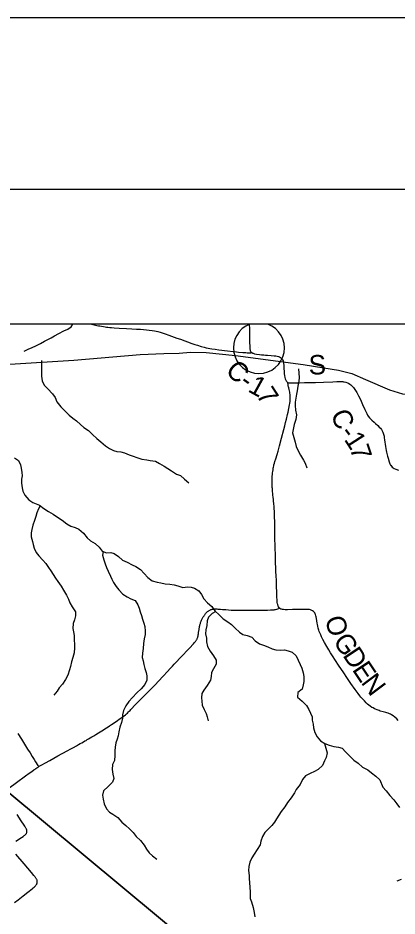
# Model space of a CAD drawing. Extents: x 0 to 34, y 0 to 22.
# Drawn here: x 21.722 to 22.828, y 19.377 to 22 of the extents above; entities that cross this region are included whole.
import ezdxf

# ---------------------------------------------------------------- set-up
doc = ezdxf.new("R2010")
doc.units = 0
for name, color, linetype in [('GM_X_Corporation', 7, 'Continuous'), ('GM_X_County_Road', 7, 'Continuous'), ('GM_X_County_Road_Text', 7, 'Continuous'), ('GM_X_Minor_River', 7, 'Continuous'), ('GM_X_Rail_Line', 7, 'Continuous'), ('GM_X_State_Shield', 7, 'Continuous'), ('GM_X_Township_Road', 7, 'Continuous'), ('GM_X_Unincorporated_Location', 7, 'Continuous'), ('SH_Border', 7, 'Continuous'), ('SH_Cut_Line', 7, 'Continuous')]:
    doc.layers.add(name, color=color, linetype=linetype)

msp = doc.modelspace()

# ---------------------------------------------------------------- linework, layer by layer
at = {"layer": 'GM_X_Corporation'}
for points in [[(17.597, 14.3059), (23.9625, 14.3059), (23.9625, 21.1059), (18.23, 21.1059), (18.203, 20.7746), (18.1731, 20.4696), (18.0879, 19.5959), (18.0387, 19.0962), (17.9672, 18.2605), (17.8718, 17.2256), (17.7834, 16.317), (17.7373, 15.7617), (17.7239, 15.6245), (17.6136, 14.4601)], [(23.8219, 21.1059), (19.1325, 21.1059), (19.4417, 20.9771), (20.0591, 20.7271), (20.5209, 20.5272), (20.9887, 20.3291), (21.1503, 20.1924), (21.2024, 20.1483), (21.462, 19.9289), (21.6862, 19.7442), (22.4736, 19.0897), (22.5453, 19.0171), (22.8523, 19.0143), (22.8728, 18.8666), (23.8372, 18.7818), (23.8567, 18.7798), (23.8401, 19.9225), (23.83, 20.7057)]]:
    msp.add_lwpolyline(points, close=True, dxfattribs=at)
msp.add_lwpolyline([(23.1639, 16.2517), (23.362, 16.8676), (23.4462, 17.1725), (23.5619, 17.5912), (23.566, 17.6066), (23.6615, 17.9524), (23.7107, 18.1304), (23.8507, 18.7519), (23.8567, 18.7798), (23.8372, 18.7818), (22.8728, 18.8666), (22.8523, 19.0143), (22.5453, 19.0171), (22.4736, 19.0897), (21.6862, 19.7442)], dxfattribs=at)
at = {"layer": 'GM_X_County_Road'}
for points in [[(21.9364, 21.1059), (21.9479, 21.1031), (21.9517, 21.1022), (21.9567, 21.1012), (21.961, 21.1004), (21.966, 21.0994), (21.9713, 21.0986), (21.9762, 21.0978), (21.9801, 21.0972), (21.9842, 21.0967), (21.9895, 21.0961), (21.9948, 21.0957), (22.0026, 21.0952), (22.0174, 21.0943), (22.0385, 21.0932), (22.0541, 21.0924), (22.0679, 21.0915), (22.0791, 21.0907), (22.0885, 21.0899), (22.0972, 21.0891), (22.1046, 21.0882), (22.1134, 21.087), (22.1203, 21.0859), (22.1255, 21.0849), (22.13, 21.0839), (22.1368, 21.0821), (22.1458, 21.0795), (22.1517, 21.0775), (22.1624, 21.0736), (22.1857, 21.0651), (22.1956, 21.0616), (22.2288, 21.0497), (22.2379, 21.0466), (22.2458, 21.044), (22.2566, 21.0407), (22.2647, 21.0384), (22.2709, 21.0368), (22.2768, 21.0354), (22.2813, 21.0345), (22.2871, 21.0337), (22.2968, 21.0325), (22.3078, 21.0312), (22.3332, 21.0282), (22.3501, 21.0262), (22.3595, 21.025), (22.3649, 21.0244), (22.3781, 21.0232), (22.3868, 21.0225), (22.3907, 21.0222), (22.3961, 21.0217), (22.3988, 21.0217), (22.4018, 21.0221), (22.4039, 21.0228)], [(22.4039, 21.0228), (22.4026, 21.0239), (22.4014, 21.0253), (22.4006, 21.0272), (22.3999, 21.0294), (22.3995, 21.0318), (22.3991, 21.0355), (22.399, 21.0395), (22.3989, 21.0436), (22.3988, 21.05), (22.3985, 21.0621), (22.3982, 21.0796), (22.398, 21.092), (22.3978, 21.1059)], [(22.4039, 21.0228), (22.4062, 21.0213), (22.4084, 21.0206), (22.4124, 21.0195), (22.4178, 21.0185), (22.4269, 21.0171), (22.432, 21.0165), (22.4393, 21.0157), (22.4441, 21.0152), (22.4499, 21.0148), (22.461, 21.014), (22.4696, 21.0134), (22.474, 21.0129), (22.478, 21.0121), (22.4817, 21.0111), (22.485, 21.0098), (22.4879, 21.0083), (22.4904, 21.0062), (22.4925, 21.0037), (22.4941, 21.0011), (22.4954, 20.9982), (22.4964, 20.9949), (22.497, 20.991), (22.4973, 20.9857), (22.4978, 20.9752), (22.4983, 20.9681), (22.4986, 20.9648), (22.499, 20.9607), (22.4998, 20.9553), (22.5008, 20.9504), (22.5018, 20.9465), (22.5027, 20.9441), (22.5035, 20.9424), (22.5048, 20.9398), (22.506, 20.9381), (22.5072, 20.9367), (22.5088, 20.9354), (22.5099, 20.9346)], [(22.4856, 20.276), (22.4842, 20.2773), (22.4825, 20.2797), (22.4809, 20.2829), (22.4802, 20.2846), (22.4796, 20.2869), (22.4791, 20.2893), (22.4786, 20.2928), (22.4783, 20.2967), (22.478, 20.3007), (22.4776, 20.3087), (22.4772, 20.3187), (22.4769, 20.3259), (22.4765, 20.3366), (22.4762, 20.3425), (22.4757, 20.3556), (22.4751, 20.3712), (22.4747, 20.3819), (22.4743, 20.3936), (22.4737, 20.4091), (22.4733, 20.4231), (22.4729, 20.4357), (22.4726, 20.4473), (22.4723, 20.4583), (22.4718, 20.4795), (22.4716, 20.49), (22.4711, 20.5241), (22.4709, 20.5312), (22.4708, 20.5396), (22.4705, 20.5479), (22.4701, 20.5553), (22.4699, 20.5601), (22.4696, 20.5652), (22.4691, 20.5725), (22.4684, 20.5817), (22.4678, 20.5884), (22.4673, 20.5934), (22.4666, 20.6006), (22.4659, 20.6065), (22.4654, 20.611), (22.4648, 20.6173), (22.4643, 20.6224), (22.4641, 20.626), (22.464, 20.6289), (22.4636, 20.6354), (22.4635, 20.6425), (22.4637, 20.6509), (22.4638, 20.6566), (22.464, 20.6617), (22.4643, 20.6665), (22.4649, 20.6718), (22.4653, 20.6756), (22.466, 20.6805), (22.4667, 20.6849), (22.4673, 20.6884), (22.468, 20.6918), (22.4688, 20.6951), (22.4699, 20.6996), (22.4713, 20.7043), (22.474, 20.7127), (22.4777, 20.725), (22.4806, 20.735), (22.4847, 20.75), (22.4907, 20.7724), (22.4976, 20.798), (22.5005, 20.8087), (22.5029, 20.8182), (22.5053, 20.8282), (22.5084, 20.8417), (22.5099, 20.8491), (22.5121, 20.8594), (22.5141, 20.8701), (22.5148, 20.8743), (22.5156, 20.8804), (22.5159, 20.884), (22.5162, 20.8882), (22.5163, 20.8921), (22.5162, 20.8967), (22.5159, 20.9006), (22.5155, 20.9041), (22.5151, 20.9073), (22.5142, 20.9114), (22.5133, 20.915), (22.5118, 20.9198), (22.5108, 20.9228), (22.5102, 20.9251), (22.5098, 20.9275), (22.5098, 20.9296), (22.5097, 20.9312), (22.5099, 20.9346)], [(22.5099, 20.9346), (22.5113, 20.9344), (22.513, 20.9344), (22.5146, 20.9343), (22.5219, 20.9344), (22.5325, 20.9345), (22.5436, 20.9347), (22.5583, 20.935), (22.5762, 20.9354), (22.5904, 20.9358), (22.6137, 20.9367), (22.6401, 20.9375), (22.6524, 20.9378), (22.658, 20.9379), (22.6652, 20.9379), (22.6694, 20.9378), (22.6717, 20.9376), (22.674, 20.9373), (22.6784, 20.9362), (22.6835, 20.9344), (22.6865, 20.933), (22.6903, 20.9308), (22.6934, 20.9282), (22.6973, 20.9243), (22.7006, 20.9204), (22.7047, 20.9148), (22.7101, 20.9065), (22.7158, 20.8963), (22.721, 20.8857), (22.7274, 20.8714), (22.734, 20.8566), (22.7359, 20.8525), (22.7393, 20.8447), (22.7417, 20.8402), (22.744, 20.8369), (22.7473, 20.8325), (22.7502, 20.8293), (22.754, 20.8256), (22.7611, 20.819), (22.7648, 20.8157), (22.7714, 20.8095), (22.7761, 20.8051), (22.7792, 20.8017), (22.7824, 20.7977), (22.7847, 20.7942), (22.7865, 20.7905), (22.7877, 20.7877), (22.7886, 20.7846), (22.7899, 20.7786), (22.7906, 20.7738), (22.7915, 20.7677), (22.7939, 20.7487), (22.7948, 20.7425), (22.7961, 20.7363), (22.7971, 20.7314), (22.7999, 20.72), (22.8016, 20.714), (22.8049, 20.7032), (22.8072, 20.6973), (22.8089, 20.6942)], [(22.8089, 20.6942), (22.8093, 20.6934), (22.8113, 20.6905), (22.8137, 20.6879), (22.8161, 20.6861), (22.8191, 20.6843), (22.8241, 20.6822), (22.8321, 20.6789)], [(22.8316, 19.9483), (22.8275, 19.9528), (22.8219, 19.9579), (22.8169, 19.9617), (22.812, 19.9646), (22.8086, 19.9665), (22.8054, 19.968), (22.8018, 19.9693), (22.7982, 19.9705), (22.7949, 19.9715), (22.7874, 19.9735), (22.7791, 19.9759), (22.7753, 19.9771), (22.7696, 19.9792), (22.7653, 19.981), (22.7621, 19.9826), (22.7579, 19.9848), (22.7548, 19.9866), (22.7496, 19.9902), (22.7456, 19.9932), (22.742, 19.9963), (22.7379, 20), (22.7325, 20.0053), (22.7258, 20.0124), (22.7223, 20.0162), (22.7192, 20.0203), (22.714, 20.0271), (22.7058, 20.0384), (22.6935, 20.0562), (22.6818, 20.0736), (22.6726, 20.0872), (22.657, 20.1102), (22.6484, 20.123), (22.6392, 20.1372), (22.6334, 20.1461), (22.6286, 20.1541), (22.6226, 20.1642), (22.6161, 20.1761), (22.6115, 20.1848), (22.6078, 20.1925), (22.6051, 20.1982), (22.6027, 20.2043), (22.6011, 20.2085), (22.5997, 20.2124), (22.5981, 20.218), (22.5968, 20.2237), (22.596, 20.2282), (22.5953, 20.2328), (22.5942, 20.2396), (22.5931, 20.2465), (22.5922, 20.2512), (22.5914, 20.2541), (22.5903, 20.2573), (22.5889, 20.2601), (22.5877, 20.2622), (22.5859, 20.2646), (22.5838, 20.2665), (22.5816, 20.2681), (22.5793, 20.2696), (22.5774, 20.2705), (22.575, 20.2713), (22.5726, 20.2719), (22.5704, 20.2723), (22.568, 20.2724), (22.5635, 20.2725), (22.558, 20.2726), (22.5512, 20.2724), (22.5226, 20.2719), (22.5087, 20.2717), (22.5017, 20.2717), (22.4969, 20.2719), (22.4934, 20.2722), (22.4908, 20.2729), (22.4888, 20.2738), (22.4863, 20.2753), (22.4856, 20.276)]]:
    msp.add_lwpolyline(points, dxfattribs=at)
at = {"layer": 'GM_X_Minor_River'}
for points in [[(21.7401, 21.0265), (21.7512, 21.0325), (21.7634, 21.0376), (21.7741, 21.0427), (21.7875, 21.0492), (21.7994, 21.0558), (21.8185, 21.0661), (21.8289, 21.0716), (21.8411, 21.0785), (21.8557, 21.0858), (21.8672, 21.0913), (21.8771, 21.0976), (21.8815, 21.1059)], [(21.7903, 20.9995), (21.7904, 20.9877), (21.7906, 20.9771), (21.7907, 20.9638), (21.7901, 20.9536), (21.7929, 20.9399), (21.7983, 20.928), (21.809, 20.9164), (21.8231, 20.9021), (21.8305, 20.8917), (21.8356, 20.8787), (21.8466, 20.8644), (21.8585, 20.8524), (21.8715, 20.84), (21.8816, 20.8311), (21.8928, 20.8229), (21.9039, 20.8124), (21.914, 20.8043), (21.9278, 20.7953), (21.9397, 20.7833), (21.9516, 20.772), (21.9635, 20.7619), (21.9773, 20.7499), (21.9892, 20.7428), (22.0009, 20.7365), (22.0107, 20.734), (22.022, 20.7331), (22.0329, 20.7302), (22.0461, 20.7242), (22.0581, 20.7202), (22.0686, 20.7162), (22.0837, 20.7114), (22.098, 20.7092), (22.1079, 20.7078), (22.1233, 20.7053), (22.1353, 20.6986), (22.1484, 20.6911), (22.1589, 20.6844), (22.1698, 20.677), (22.184, 20.668), (22.196, 20.664), (22.2075, 20.6527), (22.2206, 20.6422)], [(22.54, 20.9748), (22.5412, 20.963), (22.5424, 20.9497), (22.5411, 20.9391), (22.5381, 20.9247), (22.536, 20.9111), (22.5346, 20.9009), (22.5325, 20.8895), (22.5307, 20.8782), (22.5309, 20.8679), (22.5318, 20.8543), (22.5345, 20.8413), (22.5324, 20.8277), (22.5279, 20.8122), (22.5246, 20.7982), (22.5228, 20.788), (22.5264, 20.7747), (22.531, 20.7613), (22.5334, 20.7484), (22.5392, 20.7353), (22.5465, 20.7227), (22.5549, 20.7088), (22.56, 20.6993), (22.5651, 20.6863)], [(21.7117, 20.7149), (21.7233, 20.7079), (21.7288, 20.6949), (21.7308, 20.6853), (21.7332, 20.6724), (21.7338, 20.6629), (21.7321, 20.6527), (21.7318, 20.6409), (21.7338, 20.6276), (21.7363, 20.6181), (21.7421, 20.6058), (21.7532, 20.5927), (21.7651, 20.5848), (21.7749, 20.5809), (21.7851, 20.5769), (21.7977, 20.5671), (21.8112, 20.5589), (21.8243, 20.551), (21.837, 20.5421), (21.8505, 20.5331), (21.8643, 20.5229), (21.8766, 20.5155), (21.8891, 20.5118), (21.8999, 20.5067), (21.913, 20.4954), (21.9233, 20.4815), (21.9333, 20.4726), (21.9468, 20.4651), (21.9591, 20.4547), (21.968, 20.4423), (21.98, 20.4383), (21.9929, 20.4392), (22.0027, 20.436), (22.0154, 20.427), (22.0269, 20.4169), (22.0404, 20.4102), (22.0547, 20.4031), (22.0659, 20.3975), (22.079, 20.3889), (22.0905, 20.3777), (22.1005, 20.3657), (22.1136, 20.3564), (22.1279, 20.3523), (22.1385, 20.3505), (22.1513, 20.3476), (22.1645, 20.3459), (22.1774, 20.3445), (22.1883, 20.3416), (22.203, 20.3367), (22.2163, 20.3384), (22.2272, 20.3378), (22.237, 20.3349), (22.2494, 20.3271), (22.2571, 20.3163), (22.264, 20.3037), (22.2748, 20.2921), (22.2874, 20.2808), (22.2963, 20.2685), (22.3089, 20.2572), (22.3204, 20.2453), (22.3339, 20.2359), (22.3451, 20.2288), (22.3559, 20.218), (22.3681, 20.206), (22.3782, 20.1993), (22.391, 20.1964), (22.4042, 20.1912), (22.4142, 20.1808), (22.4265, 20.1722), (22.4378, 20.1678), (22.451, 20.163), (22.4637, 20.157), (22.4739, 20.1542), (22.4887, 20.1535), (22.4993, 20.1541), (22.5098, 20.152), (22.5219, 20.1475), (22.5334, 20.1375), (22.5392, 20.1248), (22.545, 20.1114), (22.5497, 20.1011), (22.5544, 20.0873), (22.5557, 20.0771)], [(21.7869, 20.5754), (21.7822, 20.5659), (21.7766, 20.5543), (21.7742, 20.5441), (21.7705, 20.5324), (21.7653, 20.5188), (21.762, 20.506), (21.7599, 20.4962), (21.7604, 20.4844), (21.764, 20.4714), (21.7664, 20.4619), (21.7689, 20.4516), (21.775, 20.4386), (21.7832, 20.4289), (21.7943, 20.4166), (21.8028, 20.4069), (21.8105, 20.3954), (21.8179, 20.3854), (21.8241, 20.3746), (21.8315, 20.3642), (21.8381, 20.3538), (21.8477, 20.3404), (21.855, 20.3285), (21.863, 20.3143), (21.8689, 20.3024), (21.8728, 20.2917), (21.8798, 20.2798), (21.8897, 20.2659), (21.8898, 20.2534), (21.8866, 20.2425), (21.8829, 20.2315), (21.8819, 20.2171), (21.8836, 20.2076), (21.8856, 20.1966), (21.8858, 20.1833), (21.8866, 20.17), (21.8868, 20.1605), (21.8861, 20.1461), (21.8824, 20.1318), (21.8784, 20.1193), (21.8751, 20.1061), (21.8718, 20.0959), (21.867, 20.0808), (21.8603, 20.0681), (21.852, 20.0546), (21.842, 20.0434), (21.8365, 20.0336), (21.8264, 20.0217)], [(21.9702, 20.4416), (21.9689, 20.4309), (21.972, 20.4176), (21.9759, 20.4061), (21.9802, 20.395), (21.9853, 20.3847), (21.9922, 20.3701), (21.9962, 20.3606), (22.0009, 20.351), (22.0083, 20.3398), (22.0157, 20.3295), (22.0275, 20.3167), (22.0406, 20.3096), (22.0511, 20.3033), (22.0635, 20.2985), (22.072, 20.2858), (22.0759, 20.2763), (22.0787, 20.2652), (22.0819, 20.2549), (22.0848, 20.2442), (22.0887, 20.2328), (22.0919, 20.2228), (22.0928, 20.2095), (22.0929, 20.1997), (22.0904, 20.1868), (22.0886, 20.1728), (22.0872, 20.1584), (22.0854, 20.1448), (22.0847, 20.1319), (22.0868, 20.122), (22.0889, 20.1121), (22.0924, 20.0999), (22.096, 20.0888), (22.0977, 20.0789), (22.0978, 20.0656), (22.0918, 20.0536), (22.0813, 20.0405), (22.069, 20.0287), (22.0558, 20.0156), (22.045, 20.0041), (22.0368, 19.991), (22.0301, 19.9778), (22.0271, 19.965), (22.0269, 19.9547), (22.024, 19.9419), (22.0188, 19.9283), (22.0159, 19.9155), (22.0145, 19.903), (22.0117, 19.8932), (22.0073, 19.8834), (22.0059, 19.8705), (22.0045, 19.8592), (22.0042, 19.8455), (22.0032, 19.8315), (21.998, 19.8195), (21.9966, 19.8055), (21.999, 19.7914), (22.0013, 19.7784), (21.9973, 19.7679), (21.985, 19.7556), (21.9711, 19.743), (21.9689, 19.7301), (21.9702, 19.7183), (21.9733, 19.705), (21.9798, 19.6905), (21.9887, 19.6808), (21.9984, 19.6742), (22.013, 19.6648), (22.0249, 19.6509), (22.0364, 19.6412), (22.0472, 19.6318), (22.0576, 19.6214), (22.0665, 19.6095), (22.0791, 19.5974), (22.0902, 19.5843), (22.0964, 19.5724), (22.1049, 19.5613), (22.1145, 19.5531), (22.1272, 19.543)], [(22.2988, 20.2663), (22.2885, 20.2607), (22.2773, 20.2495), (22.2741, 20.2393), (22.2727, 20.2261), (22.2701, 20.2129), (22.2688, 20.2011), (22.2723, 20.1882), (22.2724, 20.1775), (22.2744, 20.1642), (22.2825, 20.1508), (22.2925, 20.1373), (22.2998, 20.1242), (22.2999, 20.1125), (22.292, 20.0986), (22.2865, 20.0885), (22.2855, 20.0767), (22.2838, 20.0658), (22.2736, 20.0508), (22.2646, 20.0369), (22.2588, 20.0272), (22.257, 20.0147), (22.2579, 20.0044), (22.2592, 19.9926), (22.2654, 19.98), (22.2712, 19.9689), (22.2737, 19.9593), (22.2768, 19.9468)], [(22.5557, 20.0771), (22.5557, 20.0619), (22.554, 20.0521), (22.5507, 20.04), (22.5388, 20.0296), (22.5374, 20.0163), (22.5508, 20.0047), (22.5641, 19.9919), (22.5707, 19.98), (22.5758, 19.97), (22.5798, 19.9593), (22.5807, 19.9491), (22.5827, 19.9373), (22.584, 19.927), (22.5879, 19.9133), (22.5948, 19.9002), (22.6045, 19.8887), (22.6172, 19.8808), (22.63, 19.876), (22.6435, 19.8723), (22.6571, 19.8705), (22.6673, 19.8677), (22.6777, 19.8565), (22.6899, 19.8437), (22.7022, 19.8325), (22.7141, 19.8231), (22.7275, 19.8122), (22.7429, 19.8036), (22.7537, 19.7954), (22.7664, 19.7857), (22.7772, 19.7752), (22.7866, 19.753), (22.7962, 19.743), (22.8073, 19.7295), (22.8184, 19.7164), (22.8269, 19.7044), (22.8354, 19.694)], [(22.6166, 19.8812), (22.6199, 19.8675), (22.6242, 19.8537), (22.6209, 19.8405), (22.6162, 19.8308), (22.6102, 19.8168), (22.5982, 19.8049), (22.5871, 19.7995), (22.5741, 19.7933), (22.5611, 19.7863), (22.5521, 19.7755), (22.545, 19.7612), (22.5334, 19.747), (22.5286, 19.7365), (22.5185, 19.7223), (22.5087, 19.7088), (22.5001, 19.6961), (22.49, 19.6819), (22.4826, 19.6714), (22.4763, 19.6613), (22.4708, 19.6515), (22.463, 19.6418), (22.4533, 19.6318), (22.4425, 19.6206), (22.4358, 19.609), (22.4302, 19.5954), (22.4281, 19.5848), (22.4199, 19.5713), (22.4109, 19.5575), (22.4046, 19.5466), (22.3983, 19.5346), (22.395, 19.5214), (22.3944, 19.5096), (22.396, 19.4959), (22.3969, 19.4853), (22.3975, 19.4747), (22.3987, 19.4606), (22.3992, 19.4481), (22.399, 19.4378), (22.3995, 19.428), (22.4031, 19.4184), (22.4085, 19.402), (22.4112, 19.3871), (22.4132, 19.3749)], [(22.8401, 19.4833), (22.8275, 19.479)]]:
    msp.add_lwpolyline(points, dxfattribs=at)
at = {"layer": 'GM_X_Rail_Line'}
msp.add_lwpolyline([(21.65, 20.986), (21.8845, 21.0002), (22.0786, 21.0175), (22.1472, 21.0202), (22.1921, 21.0211), (22.2252, 21.0242), (22.2708, 21.0232), (22.3568, 21.0141), (22.5542, 20.9883), (22.6138, 20.9784), (22.6574, 20.9714), (22.6963, 20.9613), (22.7355, 20.9444), (22.8063, 20.9138), (22.844, 20.9019), (22.8817, 20.8969), (22.9224, 20.89), (22.9551, 20.891), (22.9918, 20.892), (23.0375, 20.9029), (23.1049, 20.9257), (23.3629, 21.028), (23.5306, 21.0876), (23.5726, 21.1059)], dxfattribs=at)
at = {"layer": 'GM_X_State_Shield'}
msp.add_line((22.4508, 21.1059), (22.3989, 21.1059), dxfattribs=at)
msp.add_arc((22.4249, 21.0361), 0.0744, 110.3994, 69.6006, dxfattribs=at)
at = {"layer": 'GM_X_Township_Road'}
for points in [[(21.7824, 19.8135), (21.784, 19.8145), (21.7861, 19.8157), (21.7916, 19.8188), (21.8021, 19.8247), (21.8145, 19.8315), (21.8383, 19.8447), (21.8651, 19.8593), (21.8766, 19.8656), (21.8841, 19.8697), (21.8925, 19.8744), (21.8988, 19.8779), (21.9037, 19.8806), (21.9086, 19.8834), (21.9132, 19.886), (21.9173, 19.8883), (21.9206, 19.8902), (21.9241, 19.8923), (21.9278, 19.8945), (21.9323, 19.8971), (21.9373, 19.9002), (21.9428, 19.9035), (21.9488, 19.9072), (21.9572, 19.9125), (21.9618, 19.9154), (21.9664, 19.9182), (21.9712, 19.9213), (21.9755, 19.924), (21.9799, 19.9269), (21.9848, 19.9301), (21.9893, 19.933), (21.9948, 19.9367), (21.9996, 19.9398), (22.0039, 19.9427), (22.0082, 19.9456), (22.0126, 19.9486), (22.0176, 19.952), (22.0217, 19.9549), (22.0255, 19.9576), (22.0284, 19.9598), (22.0316, 19.9621), (22.0352, 19.9649), (22.0381, 19.9674), (22.0412, 19.97), (22.0443, 19.973), (22.0467, 19.9754), (22.0488, 19.9776), (22.0512, 19.9801), (22.065, 19.9946), (22.0781, 20.0081), (22.0972, 20.0272), (22.1116, 20.042), (22.1218, 20.0526), (22.1318, 20.0635), (22.1452, 20.0779), (22.1577, 20.091), (22.1661, 20.1002), (22.1725, 20.107), (22.1773, 20.1122), (22.1822, 20.1175), (22.1957, 20.1319), (22.2221, 20.1595), (22.2342, 20.1722), (22.2372, 20.1756), (22.239, 20.1778), (22.24, 20.179), (22.2411, 20.1804), (22.2419, 20.1816), (22.2429, 20.1833), (22.2437, 20.1849), (22.2445, 20.1866), (22.245, 20.1878), (22.2456, 20.1892), (22.2463, 20.1912), (22.2467, 20.1929), (22.2472, 20.1953), (22.2478, 20.1979), (22.2483, 20.2009), (22.2489, 20.2053), (22.2501, 20.2138), (22.2504, 20.2162), (22.2508, 20.2183), (22.2511, 20.2201), (22.2515, 20.2223), (22.2522, 20.2253), (22.2528, 20.2276), (22.2533, 20.2299), (22.254, 20.2319), (22.2547, 20.2339), (22.2555, 20.236), (22.2564, 20.2383), (22.2578, 20.2414), (22.2594, 20.2447), (22.2607, 20.2471), (22.2616, 20.2488), (22.2627, 20.2505), (22.2637, 20.2524), (22.2647, 20.254), (22.2657, 20.2554), (22.2669, 20.2572), (22.2681, 20.2587), (22.2691, 20.2602), (22.2709, 20.2624), (22.2725, 20.2641), (22.2738, 20.2654), (22.2753, 20.2666), (22.2769, 20.2679), (22.2786, 20.2689), (22.2802, 20.2698), (22.2818, 20.2706), (22.2833, 20.2714), (22.285, 20.272), (22.2867, 20.2725), (22.2886, 20.2729), (22.2908, 20.2734), (22.2931, 20.2737), (22.2958, 20.2739), (22.299, 20.274), (22.3024, 20.2739), (22.3047, 20.2738), (22.3082, 20.2736), (22.3124, 20.2733), (22.3189, 20.2727), (22.3235, 20.2723), (22.3282, 20.2719), (22.336, 20.2713), (22.3439, 20.2708), (22.3519, 20.2704), (22.3586, 20.2702), (22.3637, 20.2701), (22.3701, 20.27), (22.3792, 20.27), (22.3889, 20.27), (22.3979, 20.27), (22.4075, 20.2701), (22.42, 20.2703), (22.4388, 20.2706), (22.4504, 20.2708), (22.4586, 20.271), (22.4635, 20.2711), (22.4667, 20.2714), (22.469, 20.2716), (22.471, 20.272), (22.4731, 20.2725), (22.4767, 20.2733), (22.4826, 20.2751), (22.4856, 20.276)], [(21.7213, 19.9102), (21.732, 19.8934), (21.7412, 19.8788), (21.75, 19.8648), (21.757, 19.8533), (21.7631, 19.8434), (21.7689, 19.8344), (21.7731, 19.8278), (21.7801, 19.817), (21.7824, 19.8135)], [(21.6864, 19.7436), (21.6882, 19.7453), (21.6903, 19.747), (21.6963, 19.7516), (21.7095, 19.7611), (21.7256, 19.7728), (21.736, 19.7803), (21.7443, 19.7864), (21.755, 19.7941), (21.7623, 19.7994), (21.7685, 19.8039), (21.7717, 19.8062), (21.7743, 19.808), (21.7768, 19.8098), (21.7786, 19.8111), (21.7805, 19.8123), (21.7824, 19.8135)], [(21.7155, 19.5958), (21.7321, 19.6065), (21.737, 19.6098), (21.7402, 19.612), (21.7421, 19.6136), (21.7437, 19.615), (21.7449, 19.6162), (21.746, 19.6175), (21.7466, 19.6185), (21.7471, 19.6194), (21.7476, 19.6209), (21.748, 19.6226), (21.7481, 19.6241), (21.7481, 19.6257), (21.748, 19.6272), (21.7476, 19.6285), (21.7471, 19.6297), (21.7466, 19.631), (21.7458, 19.6326), (21.745, 19.6341), (21.7439, 19.636), (21.7428, 19.6379), (21.7416, 19.6398), (21.7401, 19.6422), (21.7316, 19.6554), (21.7195, 19.6735)], [(21.7114, 19.4164), (21.7221, 19.4248), (21.7368, 19.4362), (21.7505, 19.4469), (21.7632, 19.4569), (21.7666, 19.4596), (21.769, 19.4615), (21.7706, 19.4629), (21.7718, 19.4642), (21.773, 19.4654), (21.7742, 19.4669), (21.7751, 19.4681), (21.7759, 19.4694), (21.7766, 19.4706), (21.7771, 19.4718), (21.7776, 19.4734), (21.7779, 19.4748), (21.778, 19.4762), (21.7781, 19.4776), (21.778, 19.4788), (21.7779, 19.4802), (21.7777, 19.4812), (21.7774, 19.4822), (21.7769, 19.4836), (21.7761, 19.4852), (21.7753, 19.4867), (21.7744, 19.488), (21.7734, 19.4895), (21.7724, 19.491), (21.7711, 19.4925), (21.7684, 19.4959), (21.7617, 19.504), (21.7399, 19.5294), (21.7153, 19.5582)]]:
    msp.add_lwpolyline(points, dxfattribs=at)
at = {"layer": 'GM_X_Unincorporated_Location'}
msp.add_line((22.4249, 21.0361), (22.4249, 21.0361), dxfattribs=at)
at = {"layer": 'SH_Border'}
msp.add_lwpolyline([(1.5, 21.5), (33.5, 21.5), (33.5, 0.5), (1.5, 0.5)], close=True, dxfattribs=at)
at = {"layer": 'SH_Cut_Line'}
msp.add_lwpolyline([(0, 0), (34, 0), (34, 22), (0, 22)], close=True, dxfattribs=at)

# ---------------------------------------------------------------- texts
at = {"layer": 'GM_X_County_Road_Text'}
for s, rotation, p in [('S', 1.1879, (22.5705, 20.9583)), ('C', 316.1302, (22.3243, 20.9662)), ('-', 324.0791, (22.3645, 20.9284)), ('1', 331.1877, (22.3899, 20.9105)), ('7', 303.3415, (22.4153, 20.8986)), ('C', 292.773, (22.6331, 20.8433)), ('1', 302.728, (22.6718, 20.7694)), ('-', 306.5667, (22.6585, 20.7873)), ('7', 288.5921, (22.6892, 20.7433)), ('O', 286.5213, (22.6165, 20.245)), ('G', 304.8537, (22.6393, 20.1793)), ('D', 303.686, (22.6677, 20.1385)), ('E', 303.7144, (22.6954, 20.0969)), ('N', 306.8042, (22.7209, 20.0588))]:
    msp.add_text(s, height=0.0568, rotation=rotation, dxfattribs=at).set_placement(p)

doc.saveas('drawing.dxf')
